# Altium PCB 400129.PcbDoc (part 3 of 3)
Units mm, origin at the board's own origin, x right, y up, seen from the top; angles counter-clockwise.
Board outline 295.85 x 54.86 mm, 2 copper layers (Top Layer, Bottom Layer), stack 1.671 mm thick; 222 components, 127 nets, 693 pads, 1827 vias.
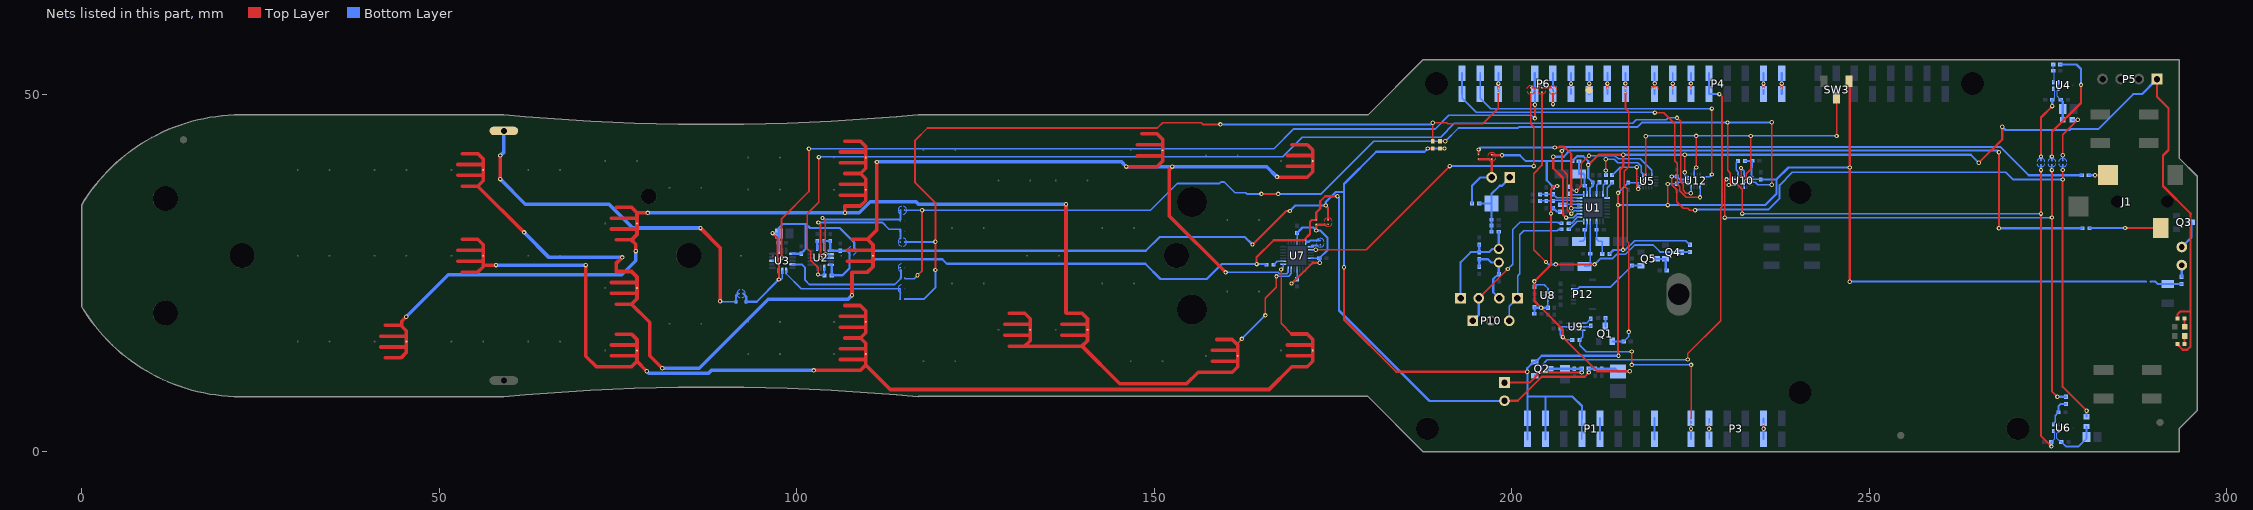
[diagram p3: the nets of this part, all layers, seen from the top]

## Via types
v1: diameter 0.61, hole 0.305, Top Layer to Bottom Layer, tented both sides, 1823 vias
v2: diameter 0.6, hole 0.3, Top Layer to Bottom Layer, tented both sides, 4 vias

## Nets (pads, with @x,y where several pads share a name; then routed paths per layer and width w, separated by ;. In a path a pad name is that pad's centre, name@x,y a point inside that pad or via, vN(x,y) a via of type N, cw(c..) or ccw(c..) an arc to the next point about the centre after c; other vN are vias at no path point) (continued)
KEYOUT_5: K6.2 K14.2 K19.2 K26.2 K31.2 K37.2 K45.2 U7.20 | length 159.3
  Top Layer w0.203: 161.659,14.956 161.659,15.218 v1(162.244,15.803) ; v1(165.538,19.089) 165.538,21.454 167.081,22.997 v1(167.081,24.547)
  Top Layer w0.508: 44.78,17.585 44.78,18.284 v1(45.385,18.89) ; 76.897,29.646 77.49,29.053 v1(77.49,28.079) ; 77.659,33.456 79.144,33.456 v1(79.173,33.428) ; 106.738,34.377 106.738,33.433 v1(106.74,33.431) ; 131.897,14.797 137.738,14.797 ; v1(137.659,34.625) 137.659,19.447 137.738,19.369 ; 139.897,14.797 145.168,9.526 154.511,9.526 156.131,11.146 158.738,11.146
  Bottom Layer w0.203: v1(162.244,15.803) 162.252,15.803 v1(165.538,19.089) ; v1(167.081,24.547) 167.124,24.59 168.77,24.59 168.838,24.658 168.847,24.648 169.157,24.959 U7.20@169.157,25.536
  Bottom Layer w0.508: v1(45.385,18.89) 51.267,24.772 75.548,24.772 77.49,26.714 v1(77.49,28.079) ; v1(79.173,33.428) v1@106.708,33.428 ; v1(106.74,33.431) 108.748,33.431 110.28,34.963 116.675,34.963 117.014,34.625 v1(137.659,34.625)
KEYOUT_6: K7.2 K15.2 K27.2 K38.2 K46.2 U7.21 | length 171.4
  Top Layer w0.508: 55.397,37.146 55.41,37.146 61.854,30.702 v1(61.88,30.702) ; 74.738,25.218 74.738,26.345 v1(75.593,27.199) ; 76.897,20.646 79.433,18.11 79.433,13.454 v1(81.189,11.698) ; v1(107.727,21.916) 107.727,25.127 107.742,25.142 107.738,25.146 ; 109.897,29.718 111.202,31.023 v1(111.202,40.53) ; v1(146.081,39.893) 146.084,39.896 148.238,39.896 ; v1(152.513,39.896) 152.117,39.5 152.117,32.968 v1(159.977,25.107) ; v1(167.173,38.455) 167.232,38.396 169.238,38.396
  Bottom Layer w0.203: v1(159.977,25.107) 167.336,25.107 167.5,24.943 168.504,24.943 168.757,25.197 U7.21@168.757,25.536
  Bottom Layer w0.508: v1(61.88,30.702) 61.88,30.676 65.356,27.199 v1(75.593,27.199) ; v1(81.189,11.698) 86.35,11.698 96.005,21.353 107.164,21.353 v1(107.727,21.916) ; v1(111.202,40.53) 111.269,40.597 145.377,40.597 v1(146.081,39.893) 165.735,39.893 v1(167.173,38.455)
KEYOUT_7: K8.2 K16.2 K20.2 K28.2 K47.2 U7.22 | length 136
  Top Layer w0.203: v1(167.731,25.5) 167.731,17.987 169.238,16.48
  Top Layer w0.508: 56.159,25.908 56.366,26.115 v1(57.943,26.115) ; v1(70.495,26.117) 70.509,26.103 70.509,13.392 72.006,11.896 74.738,11.896 ; 77.659,12.658 v1@79.032,11.285 ; v1(102.376,11.396) 106.738,11.396 ; 109.659,13.432 109.659,12.154 113.09,8.722 166.052,8.722 169.238,11.908
  Bottom Layer w0.203: v1(167.731,25.5) 168.032,25.801 U7.22@168.032,26.261
  Bottom Layer w0.508: v1(57.943,26.115) v1(57.943,26.115) v1(70.495,26.117) ; v1(79.037,11.289) 79.314,11.012 87.652,11.012 88.036,11.396 v1(102.376,11.396)
LIS3DH_INT1: P6.6 U3.11 | length 128.3
  Top Layer w0.254: v1(97.886,27.134) 97.886,32.602 101.702,36.418 v1(101.702,42.393) ; v1(203.225,46.634) v1(203.225,48.539)
  Bottom Layer w0.254: U3.11@96.599,26.721 97.279,26.721 97.692,27.134 v1(97.886,27.134) ; v1(101.702,42.393) 166.743,42.393 169.511,45.16 179.503,45.16 179.507,45.156 189.267,45.156 191.189,47.078 202.746,47.078 203.194,46.63 203.221,46.63 v1(203.225,46.634) ; P6.6@203.196,50.038 203.225,50.009 v1(203.225,48.539)
  Bottom Layer w0.305: P6.6@203.196,50.038 P6.6@203.196,52.968
MIC_CLK: R24.1 SB34.2 U10.7 | length 86.2
  Top Layer w0.203: v1(229.766,32.759) v1(229.766,32.759) 229.768,37.861 v1(230.019,38.112)
  Top Layer w0.254: v1(275.514,39.402) 275.514,8.478 v1(276.283,7.71)
  Bottom Layer w0.203: v1@229.766,32.769 v1(275.515,32.769) ; v1(230.019,38.112) 231.042,38.112 U10.7@231.049,38.105 ; v1(275.514,39.402) 275.514,39.963 SB34.2@275.514,40.137
  Bottom Layer w0.305: v1(276.283,7.71) R24.1@277.507,7.709
MIC_DOUT: C44.2 SB35.2 U6.4 U10.11 | length 92.2
  Top Layer w0.203: v1(232.048,39.698) 232.048,38.674 231.47,38.095 231.47,37.494 232.212,36.751 232.212,33.322 v1(232.213,33.32)
  Top Layer w0.254: v1(273.988,39.402) 273.988,2.236 v1(275.449,0.775)
  Bottom Layer w0.152: C44.2@275.449,1.388 275.892,1.832 275.892,2.758 U6.4@275.713,2.936
  Bottom Layer w0.203: v1(232.048,39.698) 232.474,39.272 U10.11@232.474,38.73 ; v1@232.213,33.325 v1(274,33.323) v1(274,33.323)
  Bottom Layer w0.254: v1(273.988,39.402) SB35.2@273.988,40.137 ; v1(275.449,0.775) C44.2@275.449,1.388
NetBat1_1: Bat1.1 D1.1 SB7.2 | length 52.8
  Top Layer w0.508: v1(58.547,38.151) 58.551,38.155 v1(58.551,41.444) ; v1(86.546,31.296) 89.281,28.561 v1(89.281,21.057)
  Bottom Layer w0.254: v1(89.281,21.057) 89.329,21.008 D1.1@91.528,21.008 91.528,21.927 91.735,22.134 SB7.2@91.903,22.134
  Bottom Layer w0.508: v1(58.547,38.151) 62.052,34.646 72.307,34.646 72.31,34.642 73.742,34.642 77.083,31.301 86.541,31.301 v1(86.546,31.296) ; v1(58.551,41.444) 59.05,41.943 Bat1.1@59.05,44.882
NetC2_2: C2.2 C3.2 P2.1 Q2.3 R3.1 | length 16.5
  Top Layer w0.305: P2.1@198.973,9.952 199.234,9.691 202.495,9.691 203.905,11.101 v1(209.773,11.101)
  Bottom Layer w0.305: Q2.3@205.294,11.624 207.425,11.624 C2.2@207.438,11.637 207.44,11.635 C3.2@208.743,11.635 208.746,11.633 R3.1@209.773,11.633 v1(209.773,11.101)
NetC6_2: C6.2 R4.2 U10.13 | length 3.2
  Bottom Layer w0.254: U10.13@233.499,38.505 233.499,39.678 233.598,39.778 C6.2@233.598,40.695
  Bottom Layer w0.305: R4.2@232.617,40.695 C6.2@233.598,40.695
NetC7_1: C7.1 C8.2 C9.2 P9.1 R5.1 R6.2 | length 10.8
  Bottom Layer w0.305: R5.1@195.439,34.74 197.151,34.74 C7.1@197.157,34.734 ; R6.2@197.161,30.789 197.161,31.654 C8.2@197.157,31.658 197.157,32.492 C7.1@197.157,34.734 ; P9.1@199.461,38.381 P9.1@199.722,38.381 199.722,38.335 198.614,37.227 198.307,37.227 197.166,36.086 C7.1@197.166,34.726 C7.1@197.157,34.734
NetC10_1: C10.1 J1.2 | length 2.7
  Top Layer w0.305: v1(281.543,38.699) 281.546,38.696 J1.2@283.355,38.696
  Bottom Layer w0.305: C10.1@280.693,38.689 280.703,38.699 v1(281.543,38.699)
NetC10_2: C10.2 U1.24 | length 85.2
  Top Layer w0.254: v1@207.012,42.085 207.012,39.508 207.741,38.78 207.741,33.853 208.27,33.323 v1(208.322,33.323)
  Bottom Layer w0.203: v1(208.322,33.323) 208.322,33.351 208.498,33.528 208.53,33.528 208.717,33.714 209.47,33.714 U1.24@209.475,33.709
  Bottom Layer w0.305: v1(207.001,42.085) 207.536,42.62 268.347,42.62 272.278,38.689 C10.2@279.693,38.689
NetC11_1: C11.1 J1.3 | length 10
  Top Layer w0.305: v1(285.76,31.303) 285.767,31.296 J1.3@290.755,31.296
  Bottom Layer w0.305: C11.1@280.786,31.281 280.808,31.303 v1(285.76,31.303)
NetC11_2: C11.2 U1.23 | length 96.5
  Top Layer w0.305: v1@205.797,41.367 205.797,39.662 207.159,38.3 207.159,33.191 v1(207.585,32.765) ; v1(268.111,31.281) v1(268.111,41.91)
  Bottom Layer w0.203: v1(207.585,32.765) 207.583,32.767 208.553,32.767 209.044,33.259 U1.23@209.475,33.259
  Bottom Layer w0.305: v1(205.797,41.267) 207.247,41.267 208.117,42.137 267.884,42.137 v1(268.111,41.91) ; v1(268.111,31.281) C11.2@279.786,31.281
NetC12_1: C12.1 JP1.2 P10.1 | length 22.4
  Top Layer w0.254: JP1.2@195.375,21.502 v1(199.446,25.573)
  Bottom Layer w0.254: v1(199.446,25.573) 200.13,26.257 200.13,31.104 201.144,32.118 206.421,32.118 206.543,31.996 C12.1@206.958,31.996
  Bottom Layer w0.305: P10.1@194.551,18.321 195.375,19.145 JP1.2@195.375,21.502
NetC12_2: C12.2 U1.22 | length 1.9
  Bottom Layer w0.203: C12.2@207.958,31.996 208.348,31.996 209.161,32.809 U1.22@209.475,32.809
NetC13_2: C13.2 R10.1 R11.2 U1.27 | length 5.5
  Bottom Layer w0.203: R11.2@203.925,35.242 204.078,35.089 C13.2@204.68,35.089 ; C13.2@204.832,35.089 R10.1@205.725,35.09 ; R10.1@205.776,35.168 208.468,35.168 208.578,35.059 U1.27@209.475,35.059
NetC14_2: C14.2 R9.1 R13.2 U1.28 | length 5.9
  Bottom Layer w0.203: R13.2@203.925,36.025 C14.2@204.832,36.025 R9.1@205.725,36.025 ; R9.1@205.725,36.177 205.668,36.12 206.266,35.522 209.462,35.522 U1.28@209.475,35.509
NetC15_2: C15.2 C16.2 JP1.1 P11.1 R6.1 | length 14.6
  Bottom Layer w0.305: JP1.1@192.835,21.502 192.835,26.528 194.241,27.934 C16.2@195.451,27.934 ; C15.2@195.452,28.986 C16.2@195.451,27.934 C16.2@195.451,27.934 ; R6.1@198.161,30.789 198.161,28.4 P11.1@198.179,28.382 197.262,28.382 196.815,27.934 C16.2@195.451,27.934
NetC16_1: C16.1 C18.2 JP2.2 P11.2 R17.2 | length 9.7
  Bottom Layer w0.305: C18.2@195.449,25.882 195.451,25.884 C16.1@195.451,26.934 196.66,26.934 197.113,26.482 P11.2@198.179,26.482 ; P11.2@198.178,26.481 R17.2@198.178,24.848 198.088,24.848 197.41,24.17 197.41,22.33 JP2.2@198.246,21.494
NetC17_1: C17.1 JP2.1 P10.3 | length 18.8
  Bottom Layer w0.254: P10.3@199.631,18.321 199.631,20.341 200.784,21.494 JP2.1@200.786,21.494 200.839,21.546 200.839,24.652 201.109,24.923 201.109,30.391 201.635,30.917 206.337,30.917 206.541,31.121 C17.1@206.958,31.121
NetC17_2: C17.2 U1.21 | length 2.6
  Bottom Layer w0.203: C17.2@207.958,31.121 208.008,31.121 209.121,32.234 U1.21@210.05,32.234
NetC19_1: C19.1 C23.2 FB1.1 U1.2 | length 5.4
  Bottom Layer w0.203: C23.2@210.187,37.234 210.5,36.921 U1.2@210.5,36.084
  Bottom Layer w0.305: FB1.1@209.396,40.658 209.396,38.897 C19.1@209.391,38.891 209.978,38.891 210.161,38.708 210.161,37.234 C23.2@210.187,37.234
NetC20_1: C20.1 C25.2 R12.1 U1.17 | length 5.2
  Bottom Layer w0.203: U1.17@211.85,32.234 211.85,31.086 C25.2@211.853,31.083 211.853,29.727 212.146,29.433 C20.1@212.664,29.433 212.659,29.428 R12.1@212.659,27.691
NetC21_1: C21.1 C26.2 U1.19 | length 7
  Bottom Layer w0.203: C21.1@210.145,25.957 210.739,25.957 210.947,26.164 C26.2@210.947,27.734 210.95,27.738 U1.19@210.95,32.234
NetC22_1: C22.1 C27.2 U1.20 | length 3.5
  Bottom Layer w0.203: C22.1@209.41,29.433 209.902,29.433 210.212,29.744 C27.2@210.212,31.083 210.5,31.371 U1.20@210.5,32.234
NetC34_2: C34.2 U2.14 | length 1.1
  Bottom Layer w0.305: U2.14@102.856,28.366 C34.2@102.856,29.485
NetC35_2: C35.2 C36.2 FB2.1 U4.2 U4.3 | length 5.7
  Bottom Layer w0.152: U4.2@276.41,51.703 U4.3@276.41,50.803 276.41,50.692 276.24,50.522 276.24,49.762 276.738,49.264 C35.2@276.778,49.264
  Bottom Layer w0.305: C35.2@276.778,49.264 277.035,49.006 C36.2@277.035,47.969 277.035,46.434 FB2.1@277.041,46.428
NetC37_2: C37.2 R23.2 SB28.2 | length 4.5
  Bottom Layer w0.305: SB28.2@289.345,23.819 289.981,23.819 290.316,23.484 C37.2@291.719,23.484 291.728,23.492 R23.2@293.674,23.492
NetC39_2: C39.2 SB35.1 U4.4 | length 10.9
  Top Layer w0.305: v1(273.99,41.302) 273.99,46.76 v1(275.581,48.351)
  Bottom Layer w0.152: C39.2@275.59,49.268 275.944,49.622 275.944,50.453 275.71,50.687 U4.4@275.71,50.803
  Bottom Layer w0.305: SB35.1@273.988,40.762 273.988,40.937 273.988,41.3 v1(273.99,41.302) ; v1(275.581,48.351) 275.581,49.259 C39.2@275.59,49.268
NetC40_2: C40.2 R22.2 U4.1 | length 2.6
  Bottom Layer w0.152: R22.2@275.701,54.174 C40.2@275.701,53.285 275.88,53.107 275.88,52.024 275.71,51.854 U4.1@275.71,51.703
NetC42_2: C42.2 C43.2 FB3.1 U6.3 | length 7.9
  Bottom Layer w0.152: U6.3@276.413,2.936 276.413,2.84 276.183,2.609 276.183,1.925 276.72,1.388 C42.2@276.838,1.388
  Bottom Layer w0.254: C42.2@276.838,1.388 277.453,0.772 279.273,0.772 279.636,1.135 280.373,1.873 C43.2@280.373,2.08 FB3.1@280.373,3.56
NetC45_2: C45.2 R24.2 U6.1 | length 4.1
  Bottom Layer w0.203: U6.1@275.713,3.836 275.713,3.962 275.987,4.235 275.987,5.082 C45.2@276.438,5.533
  Bottom Layer w0.305: C45.2@276.438,5.533 276.429,5.542 276.429,6.38 276.759,6.709 R24.2@277.507,6.709
NetC46_2: C46.2 C47.2 C48.2 SB29.2 SB30.2 U7.4 U7.12 U7.18 | length 21.1
  Top Layer w0.305: v1(169.185,23.55) 169.242,23.55 172.143,26.452 v1(173.126,26.452) ; v1(172.652,30.961) 172.655,30.964 172.655,31.756 173.912,31.756 173.963,31.807
  Bottom Layer w0.203: U7.18@169.957,25.536 169.957,24.132 C47.2@169.96,24.129 ; U7.4@169.957,29.386 C46.2@169.957,30.442 ; U7.12@171.882,27.061 171.885,27.064 C48.2@173.083,27.064
  Bottom Layer w0.305: v1(169.185,23.55) 169.237,23.55 169.816,24.129 C47.2@169.96,24.129 ; C46.2@169.953,30.612 170.725,31.384 172.229,31.384 v1(172.652,30.961) 172.672,30.941 173.233,30.941 174.225,29.949 174.225,28.205 C48.2@173.083,27.064 173.126,27.021 v1(173.126,26.452)
NetC49_1: C49.1 U9.4 | length 1.4
  Bottom Layer w0.254: U9.4@209.907,18.003 210.438,18.003 C49.1@211.057,18.622
NetC49_2: C49.2 U9.5 | length 1.2
  Bottom Layer w0.254: U9.5@209.907,17.503 210.938,17.503 C49.2@211.057,17.622
NetFB2_2: FB2.2 SB27.2 | length 7.3
  Top Layer w0.254: v1(277.038,41.478) 277.038,44.331 v1(279.144,46.437)
  Bottom Layer w0.254: v1(277.038,41.478) 277.041,41.475 SB27.2@277.041,40.767
  Bottom Layer w0.305: FB2.2@278.391,46.428 278.397,46.435 v1(279.144,46.437)
NetLD1_1: LD1.1 Q3.3 | length 4
  Bottom Layer w0.305: LD1.1@293.691,28.661 295.049,30.018 Q3.3@295.049,32.098
NetLD1_2: LD1.2 R23.1 | length 1.6
  Bottom Layer w0.305: R23.1@293.674,24.492 293.674,26.104 LD1.2@293.691,26.121
NetLD3_2: LD3.2 R36.1 | length 1.1
  Top Layer w0.305: LD3.2@294.068,16.219 294.073,16.215 R36.1@294.073,15.088
NetLD4_2: LD4.2 R37.1 | length 1.2
  Top Layer w0.305: LD4.2@294.068,17.503 294.068,18.664 R37.1@294.073,18.669
NetP3_1: P3.1 SB14.2 | length 3.5
  Top Layer w0.203: v1(225.044,3.243) 225.081,3.28 225.081,3.627 SB14.2@225.081,3.802
  Bottom Layer w0.254: P3.1@225.04,1.778 P3.1@225.04,4.708
NetP3_2: P3.2 SB1.2 | length 3.5
  Top Layer w0.203: v1(227.593,3.243) 227.622,3.272 SB1.2@227.622,3.802
  Bottom Layer w0.203: P3.2@227.58,1.778 P3.2@227.58,4.708
NetP3_5: P3.5 SB2.2 | length 3.5
  Top Layer w0.254: v1(235.204,3.243) 235.211,3.25 SB2.2@235.211,3.802
  Bottom Layer w0.254: P3.5@235.2,1.778 P3.5@235.2,4.708
NetP4_1: P4.1 SB33.2 | length 3.5
  Top Layer w0.305: SB33.2@237.739,50.927 v1(237.739,51.502)
  Bottom Layer w0.305: P4.1@237.74,50.038 P4.1@237.74,52.968
NetP4_2: P4.2 SB3.2 | length 3.5
  Top Layer w0.305: SB3.2@235.196,50.932 v1(235.196,51.498)
  Bottom Layer w0.305: P4.2@235.2,50.038 P4.2@235.2,52.968
NetP4_6: P4.6 SB4.2 | length 3.5
  Top Layer w0.254: v1(225.04,51.511) 225.044,51.507 225.044,51.102 SB4.2@225.044,50.927
  Bottom Layer w0.305: P4.6@225.04,50.038 v1(225.04,51.511) P4.6@225.04,52.968
NetP4_7: P4.7 SB5.2 | length 3.5
  Top Layer w0.254: SB5.2@222.5,50.935 222.5,51.11 v1(222.5,51.503)
  Bottom Layer w0.254: P4.7@222.5,50.038 v1(222.5,51.503) P4.7@222.5,52.968
NetP4_8: P4.8 SB6.2 | length 3.6
  Top Layer w0.305: SB6.2@219.96,50.876 219.96,51.051 219.96,51.524 v1(219.975,51.539)
  Bottom Layer w0.305: P4.8@219.96,50.038 P4.8@219.96,52.968
NetP6_1: P6.1 SB10.2 | length 3.6
  Top Layer w0.305: v1(215.88,51.521) 215.885,51.516 SB10.2@215.885,50.877
  Bottom Layer w0.305: P6.1@215.896,50.038 P6.1@215.896,52.968
NetP6_2: P6.2 SB9.2 | length 3.5
  Top Layer w0.305: SB9.2@213.346,50.928 213.346,51.493 v1(213.356,51.503)
  Bottom Layer w0.305: P6.2@213.356,50.038 v1(213.356,51.503) P6.2@213.356,52.968
NetP6_3: P6.3 TP2.1 | length 3.9
  Top Layer w0.305: TP2.1@210.816,50.579 v1(210.816,51.503)
  Bottom Layer w0.305: P6.3@210.816,50.038 v1(210.816,51.503) P6.3@210.816,52.968
NetP6_4: P6.4 SB32.2 | length 3.5
  Top Layer w0.203: v1(208.276,51.503) 208.28,51.499 208.28,51.158 SB32.2@208.28,50.983
  Bottom Layer w0.254: P6.4@208.276,50.038 v1(208.276,51.503) P6.4@208.276,52.968
NetP6_5: P6.5 SB11.2 | length 6
  Top Layer w0.305: SB11.2@205.741,50.305 205.741,50.13 205.741,48.64 v1(205.753,48.629)
  Bottom Layer w0.305: P6.5@205.736,52.968 P6.5@205.736,50.038 205.753,50.021 v1(205.753,48.629)
NetP6_8: P6.8 SB12.2 | length 3.6
  Top Layer w0.305: SB12.2@198.102,50.879 198.102,51.489 v1@198.115,51.502
  Bottom Layer w0.305: P6.8@198.116,50.038 v1(198.116,51.503) P6.8@198.116,52.968
NetP9_2: P9.2 R5.2 SB15.2 SB16.2 | length 9.8
  Top Layer w0.305: SB16.2@195.34,40.912 196.876,40.912 ; P9.2@197.182,38.381 197.195,38.394 197.195,40.778 SB15.2@197.195,40.952
  Bottom Layer w0.305: R5.2@194.439,34.74 194.439,37.231 195.589,38.381 P9.2@197.182,38.381
NetQ1_1: Q1.1 R31.2 SB10.1 | length 37.4
  Top Layer w0.254: SB10.1@215.885,50.252 215.885,48.046 216.338,47.592 216.338,39.836 215.727,39.225 215.727,37.225 216.129,36.823 216.129,29.44 216.358,29.211 216.358,16.796 v1(216.35,16.789)
  Bottom Layer w0.254: Q1.1@214.034,15.457 215.255,15.457 215.273,15.439 215.65,15.439 216.35,16.14 v1(216.35,16.789)
NetQ1_3: Q1.3 R2.1 | length 1.2
  Bottom Layer w0.254: Q1.3@213.084,17.557 213.1,17.573 R2.1@213.1,18.707
NetQ4_1: Q4.1 Q5.3 R34.2 | length 3.3
  Bottom Layer w0.305: Q5.3@220.176,26.996 Q4.1@221.492,26.995 221.221,26.995 221.516,26.7 R34.2@221.516,25.36
NetQ4_3: Q4.3 R33.2 SB38.1 | length 46.7
  Top Layer w0.254: SB38.1@204.203,50.31 204.203,50.135 204.203,40.067 203.06,38.925 203.06,28.272 v1(204.778,26.554) ; v1(206.145,26.221) v1(211.571,26.221)
  Bottom Layer w0.254: v1(204.778,26.554) 205.111,26.221 v1(206.145,26.221) ; v1(211.571,26.221) 212.384,27.034 214.046,27.034 214.656,27.643 215.895,27.643 217.185,28.933 219.757,28.933 220.74,27.951 223.583,27.951 223.585,27.953 Q4.3@223.592,27.945 ; Q4.3@223.6,27.953 R33.2@224.888,27.953
  Bottom Layer w0.305: Q4.3@223.592,27.945 Q4.3@223.6,27.953
NetR4_1: R4.1 U10.9 | length 2.2
  Bottom Layer w0.203: R4.1@231.617,40.695 231.385,40.463 231.385,39.424 231.674,39.135 U10.9@231.674,38.73
NetR7_1: R7.1 R8.2 U1.26 | length 2.8
  Bottom Layer w0.203: R7.1@206.705,34.628 207.573,34.628 207.592,34.609 208.029,34.609 208.061,34.64 209.444,34.64 U1.26@209.475,34.609
NetR14_1: R14.1 U5.4 | length 17.2
  Top Layer w0.203: v1(209.044,36.521) 209.719,37.196 209.719,40.359 v1(210.782,41.422)
  Bottom Layer w0.203: R14.1@208.066,37.091 208.636,36.521 v1(209.044,36.521) ; v1(210.782,41.422) 210.805,41.446 214.398,41.446 214.853,40.99 217.922,40.99 219.536,39.377 U5.4@219.536,38.68
NetR14_2: R14.2 U1.1 | length 2.1
  Bottom Layer w0.203: R14.2@208.066,36.091 208.169,35.988 210.039,35.988 210.05,35.999 U1.1@210.05,36.084
NetR15_1: R15.1 U1.5 | length 1.8
  Bottom Layer w0.203: U1.5@211.85,36.084 211.85,37.301 R15.1@212.241,37.691
NetR16_1: R16.1 U5.1 | length 8.9
  Top Layer w0.203: v1(213.138,40.912) 213.138,39.36 v1(213.144,39.355)
  Bottom Layer w0.203: R16.1@213.138,38.708 213.144,38.713 v1(213.144,39.355) ; v1(213.138,40.912) 214.323,40.912 214.805,40.431 217.615,40.431 218.086,39.96 218.086,39.135 218.336,38.885 U5.1@218.336,38.68
NetR16_2: R16.2 U1.7 | length 1.8
  Bottom Layer w0.203: U1.7@212.75,36.084 212.75,37.32 R16.2@213.138,37.708
NetR18_1: R18.1 U5.13 | length 7.2
  Top Layer w0.203: 217.465,37.028 v1(217.465,39.825)
  Bottom Layer w0.203: R18.1@214.023,38.714 215.133,39.825 v1(217.465,39.825) ; v1(217.679,36.782) 217.711,36.814 U5.13@217.711,37.255
NetR18_2: R18.2 U1.8 | length 2.5
  Bottom Layer w0.203: U1.8@213.325,35.509 213.325,36.925 214.023,37.622 R18.2@214.023,37.714
NetR19_1: R19.1 U2.6 U12.12 | length 154.7
  Top Layer w0.203: v1(102.978,24.811) 102.978,25.775 101.956,26.797 101.956,27.976 101.488,28.443 101.488,33.285 103.099,34.896 v1(103.099,41.224) ; v1(223.092,46.708) 223.585,46.215 223.585,37.796 223.947,37.433 223.947,36.573 224.351,36.17 v1(225.019,36.17) ; v1(103.099,41.224) 103.038,41.224 103.099,41.284 v1(103.099,41.224)
  Bottom Layer w0.203: v1(102.978,24.811) 103.096,24.693 103.712,24.693 103.856,24.837 U2.6@103.856,25.741 ; v1(103.099,41.224) 103.153,41.279 167.942,41.279 170.698,44.035 190.04,44.035 191.936,45.931 216.876,45.931 217.406,46.461 221.591,46.461 221.838,46.708 v1(223.092,46.708) ; v1(225.019,36.17) 225.116,36.267 U12.12@225.116,37.08
NetR20_1: R20.1 SB22.1 SB25.2 U10.5 U10.15 | length 161.4
  Top Layer w0.203: v1(230.166,46.072) 230.166,39.355 230.553,38.968 230.553,37.545 v1(230.323,37.315) ; v1(236.347,37.368) v1@236.395,37.415
  Top Layer w0.254: v1(116.886,24.7) 117.534,25.347 v1(117.534,33.781) ; v1(164.977,36.083) 167.335,36.083 v1(167.336,36.082) ; R20.1@189.949,43.435 v1(190.676,43.435) ; v1(236.347,37.368) v1(236.347,46.086)
  Bottom Layer w0.203: v1(230.323,37.315) 230.333,37.305 U10.5@231.049,37.305 ; U10.15@233.499,37.705 234.056,37.705 234.393,37.368 v1(236.347,37.368)
  Bottom Layer w0.254: SB22.1@115.138,33.781 115.046,33.782 v1(117.534,33.781) ; 115.143,24.217 116.404,24.217 v1(116.886,24.7) ; v1(117.534,33.781) 149.473,33.781 153.244,37.552 159.114,37.552 159.306,37.744 159.769,37.744 161.282,36.231 162.805,36.231 162.954,36.082 v1(164.977,36.083) v1(164.977,36.083) ; v1(167.336,36.082) 173.357,36.082 180.711,43.435 v1(190.676,43.435) 192.536,45.296 200.864,45.296 200.987,45.418 217.556,45.418 218.209,46.072 v1(230.166,46.072) 230.175,46.062 236.323,46.062 v1(236.347,46.086)
NetR21_1: R21.1 SB12.1 SB23.1 SB26.2 | length 119.5
  Top Layer w0.254: v1(119.383,25.444) v1(119.383,29.386) 119.383,34.83 116.547,37.665 116.547,43.557 118.288,45.297 150.421,45.297 151.154,46.03 151.159,46.026 156.539,46.026 156.771,45.794 v1(159.241,45.794) ; R21.1@188.943,43.435 v1(188.943,46.027) 190.896,46.027 191.041,45.882 195.929,45.882 198.102,48.055 SB12.1@198.102,50.254
  Bottom Layer w0.254: SB26.2@115.095,21.366 117.784,21.366 119.383,22.965 v1(119.383,25.444) ; SB23.1@115.11,29.347 119.344,29.347 v1(119.383,29.386) ; v1(159.241,45.794) 188.71,45.794 v1(188.943,46.027)
NetR22_1: R22.1 SB34.1 | length 17.6
  Top Layer w0.305: v1(275.515,41.302) 275.515,44.726 279.591,48.801 v1(279.591,51.329)
  Bottom Layer w0.305: SB34.1@275.514,40.762 275.514,40.937 275.514,41.301 v1(275.515,41.302) ; R22.1@276.701,54.174 278.974,54.174 279.6,53.549 279.591,53.54 v1(279.591,51.329)
NetR25_1: R25.1 SB14.1 U9.6 | length 27.9
  Top Layer w0.203: v1(216.758,12.166) 216.764,12.172 v1(216.764,14.046) ; v1(225.069,12.167) 225.081,12.155 SB14.1@225.081,4.477
  Bottom Layer w0.203: U9.6@209.907,17.003 209.907,16.104 R25.1@209.467,15.664 209.467,14.888 210.375,13.98 216.765,13.98 216.765,14.044 v1(216.764,14.046) ; v1(216.758,12.166) v1(225.069,12.167)
NetR26_1: R26.1 U7.23 | length 1.6
  Bottom Layer w0.203: R26.1@166.681,26.169 167.173,26.661 U7.23@168.032,26.661
NetSB19_1: SB19.1 SB25.1 U3.4 | length 18.7
  Bottom Layer w0.254: U3.4@99.399,26.221 100.686,26.221 101.16,25.747 101.16,24.008 101.759,23.409 113.71,23.409 114.37,24.068 ; 114.518,24.217 114.574,24.273 114.574,24.607 114.574,25.085 114.574,25.438
NetSB20_1: SB20.1 SB22.2 U2.2 | length 18.1
  Top Layer w0.254: v1(103.599,32.705) 103.994,32.31 v1(103.994,27.641)
  Bottom Layer w0.254: v1(103.599,32.705) 103.811,32.493 114.518,32.493 114.518,33.424 114.518,33.776 SB22.2@114.513,33.781 ; v1(103.994,27.641) U2.2@104.581,27.641
NetSB21_1: SB21.1 SB23.2 U2.3 | length 19.6
  Top Layer w0.254: v1(103.022,32.08) 103.342,31.761 v1(103.342,27.143)
  Bottom Layer w0.254: v1(103.022,32.08) 103.003,32.1 111.946,32.1 112.904,31.142 114.518,31.142 114.513,31.137 114.513,30.161 114.513,29.808 ; v1(103.342,27.143) 103.402,27.082 104.225,27.082 104.285,27.142 104.286,27.141 U2.3@104.581,27.141
NetSB24_1: SB24.1 SB26.1 U3.6 | length 18.7
  Bottom Layer w0.254: U3.6@98.499,25.321 98.499,24.943 100.619,22.823 114.17,22.823 SB24.1@114.463,22.823 114.47,22.815 114.47,22.32 SB26.1@114.47,21.366
NetSB31_1: SB31.1 U7.8 | length 0.9
  Bottom Layer w0.3: U7.8@171.942,28.721 172.102,28.881 172.796,28.881
NetSB31_2: SB31.2 U7.7 | length 2
  Bottom Layer w0.305: U7.7@171.224,29.386 171.633,29.386 171.81,29.564 172.692,29.564 SB31.2@173.187,29.564
NetSB36_2: SB36.2 U7.9 | length 46.6
  Top Layer w0.203: v1(172.569,28.265) 179.623,28.265 191.311,39.953 v1(191.311,39.962) ; SB36.2@202.648,50.305 SB36.2@202.648,50.319
  Top Layer w0.254: SB36.2@202.648,50.305 202.648,50.13 202.648,45.865 203.06,45.454 v1(203.06,39.96)
  Bottom Layer w0.152: U7.9@171.882,28.261 172.566,28.261 v1(172.569,28.265)
  Bottom Layer w0.254: v1(191.311,39.962) 191.302,39.962 191.3,39.96 v1(203.06,39.96)
NetSW3_2: SW3.2 U5.2 U10.2 U12.2 | length 52
  Top Layer w0.203: v1@218.539,37.919 v1(218.542,37.922) 218.542,38.805 218.736,38.999 v1(218.736,44.146) ; v1(225.787,39.78) v1@225.787,44.188 ; v1(232.774,37.905) 232.774,38.905 233.407,39.538 v1@233.407,44.173 ; v1(233.408,44.17) v1@233.408,44.172 ; v1(245.415,44.17) SW3.2@245.415,49.523
  Bottom Layer w0.203: v1@218.736,38.121 U5.2@218.736,38.68 ; v1(218.736,44.146) 218.777,44.188 v1(225.778,44.188) 245.397,44.188 v1(245.415,44.17) ; U12.2@225.516,38.73 225.516,39.508 v1(225.787,39.78) ; U10.2@232.474,37.08 232.474,37.591 232.774,37.891 v1(232.774,37.905)
"POWER ON/OFF": P4.5 Q2.1 | length 66.3
  Top Layer w0.254: v1(224.595,12.914) 224.595,13.757 229.208,18.37 229.208,34.115 229.403,34.311 229.403,49.648 v1(229.022,50.029)
  Bottom Layer w0.254: Q2.1@203.194,10.674 203.354,10.674 204.149,11.469 204.149,12.082 204.955,12.888 224.569,12.888 v1(224.595,12.914) ; P4.5@227.58,52.968 P4.5@227.58,50.038 229.013,50.038 v1(229.022,50.029)
SCL: P6.10 U12.9 | length 49.1
  Top Layer w0.203: v1(220.004,47.444) 221.245,47.444 222.793,45.897 222.793,40.709 223.118,40.384 223.118,37.437 223.47,37.085 223.47,36.522 224.395,35.597 v1(226.31,35.597)
  Bottom Layer w0.203: P6.10@193.036,50.038 193.036,49.445 195.006,47.474 219.974,47.474 v1(220.004,47.444) ; v1(226.31,35.597) 226.316,35.603 U12.9@226.316,37.097
  Bottom Layer w0.254: P6.10@193.036,50.038 P6.10@193.036,52.968
SDA: P6.9 U12.5 | length 46.9
  Top Layer w0.203: v1(227.977,38.795) v1(227.977,48.003)
  Bottom Layer w0.203: P6.9@195.576,49.469 197.042,48.003 220.943,48.003 v1(227.977,48.003) ; U12.5@226.941,38.505 227.687,38.505 v1(227.977,38.795)
  Bottom Layer w0.254: P6.9@195.576,49.469 P6.9@195.576,50.038 P6.9@195.576,52.968
V5V: P1.5 | length 2.9
  Bottom Layer w0.305: P1.5@212.34,1.778 P1.5@212.34,4.708
VCC: C1.1 C4.2 C5.2 C24.2 C50.2 C53.2 FB1.2 P2.2 P5.1 R3.2 R7.2 R9.2 R10.2 R12.2 R25.2 R26.2 R27.1 R28.1 R32.1 R33.1 R36.2 R37.2 SB15.1 SB17.1 SB29.1 U1.3 U8.1 U8.5 U9.2 U12.16 | length 377.1
  Top Layer w0.254: v1(224.178,39.084) 224.182,39.087 v1(224.182,41.55)
  Top Layer w0.305: v1(164.303,26.266) 164.303,27.204 166.701,29.601 170.915,29.601 171.776,30.463 171.776,32.173 172.035,32.432 SB29.1@172.655,32.432 172.655,33.479 173.207,34.031 173.207,35.051 173.91,35.753 v1(175.599,35.753) ; SB15.1@197.195,41.577 197.305,41.468 197.305,41.474 198.606,41.474 v1(198.615,41.484) ; P2.2@198.972,7.151 200.825,7.151 204.191,10.516 210.183,10.516 v1(210.767,11.101) ; v1(206.33,37.177) 205.928,37.177 205.481,36.73 205.481,33.341 v1(205.468,33.341) 205.468,26.16 v1(203.156,23.848) 203.156,21.103 v1(204.099,20.16) 207.14,17.119 v1(207.14,16.051) 211.922,11.269 v1(216.488,11.269) ; v1(210.688,40.13) 212.11,41.552 v1(215.583,41.552) 215.583,39.888 215.102,39.408 215.102,36.988 215.539,36.552 v1(215.539,28.245) ; v1(265.304,40.424) 268.573,43.694 v1(268.573,45.467) ; P5.1@290.223,52.14 290.223,49.66 291.84,48.043 291.84,42.223 291.056,41.439 291.056,37.193 294.937,33.312 294.898,33.273 294.912,33.259 294.912,19.634 ; R36.2@293.073,15.088 293.073,15.014 293.808,14.279 294.465,14.279 294.912,14.726 294.912,19.634 ; R37.2@293.073,18.669 293.073,19.236 293.472,19.634 294.912,19.634
  Bottom Layer w0.203: C50.2@205.052,20.163 U8.1@205.052,21.366 ; C53.2@206.812,17.253 207.062,17.503 U9.2@208.027,17.503 ; v1@207.14,16.059 207.535,15.664 R25.2@208.467,15.664
  Bottom Layer w0.254: R28.1@203.156,23.11 203.428,23.381 204.525,23.381 205.052,22.854 U8.5@205.052,22.466 ; v1(215.539,28.245) 215.885,28.245 217.171,29.53 224.307,29.53 R33.1@224.886,28.951 ; v1(224.178,39.084) 224.178,38.662 224.336,38.505 U12.16@224.491,38.505
  Bottom Layer w0.305: SB17.1@108.052,26.641 110.731,26.641 111.041,26.95 120.343,26.95 120.993,26.299 148.731,26.299 150.863,24.168 157.349,24.168 159.447,26.266 v1(164.303,26.266) 165.525,26.266 R26.2@165.656,26.134 ; v1(175.599,35.753) 175.819,35.533 175.819,19.786 188.493,7.112 198.972,7.112 P2.2@198.972,7.151 ; v1@198.72,41.589 v1(198.615,41.484) 201.125,41.484 201.951,40.658 FB1.2@208.446,40.658 208.446,40.678 209.11,41.342 209.985,41.342 210.688,40.639 v1(210.688,40.13) 210.688,38.34 C24.2@211.343,37.685 211.343,37.251 210.95,36.859 U1.3@210.95,36.084 ; R32.1@203.149,19.316 203.156,19.323 R27.1@203.156,20.241 203.234,20.163 C50.2@205.052,20.163 ; R28.1@203.156,23.11 v1(203.156,23.848) ; 204.871,40.658 204.871,37.968 205.662,37.177 v1(206.33,37.177) ; v1(205.468,33.341) 205.468,33.985 205.725,34.243 R10.2@205.725,34.188 ; R10.2@205.725,34.019 R10.2@205.725,34.188 ; R7.2@206.705,33.628 206.286,33.628 R10.2@205.725,34.188 ; C53.2@206.812,17.253 206.812,16.387 v1@207.14,16.059 ; v1(210.767,11.101) 210.773,11.106 R3.2@210.773,11.633 211.691,11.633 C4.2@211.693,11.631 C5.2@212.579,11.631 214.473,11.631 C1.1@214.838,11.266 216.486,11.266 v1(216.488,11.269) ; R12.2@213.659,27.691 214.213,28.245 v1(215.539,28.245) ; v1(265.304,40.424) 264.176,41.552 v1(215.583,41.552) ; v1(268.573,45.467) 269.035,45.005 278.031,45.005 278.166,45.14 281.988,45.14 286.879,50.031 288.114,50.031 P5.1@290.223,52.14 ; v1(215.583,41.552) 215.583,41.601 215.534,41.552 v1(215.583,41.552)
VCC_PDM: C52.2 FB3.2 SB27.1 U12.15 | length 100.9
  Top Layer w0.254: v1(222.354,38.505) 222.354,37.381 223.07,36.664 223.07,34.961 223.948,34.083 224.597,34.083 224.876,33.804 v1(225.629,33.804) ; v1(277.038,39.421) 277.038,38.112 277.026,38.1 277.026,9.097 v1(280.376,5.747)
  Bottom Layer w0.254: v1@222.354,38.505 C52.2@223.065,38.505 223.466,38.105 U12.15@224.491,38.105 ; v1(225.629,33.804) 225.704,33.879 235.873,33.879 237.438,35.444 237.438,37.316 239.228,39.106 269.048,39.106 270.053,38.1 v1(277.038,38.1) ; v1(277.038,39.421) 277.041,39.424 SB27.1@277.041,40.142 ; FB3.2@280.373,4.91 v1@280.373,5.718
VIN: P1.8 | length 2.9
  Bottom Layer w0.305: P1.8@219.96,1.778 P1.8@219.96,4.708
VIO: C28.2 C29.2 C33.2 C41.2 C55.2 C56.2 D1.3 P1.1 P1.2 P1.4 Q2.2 R20.2 R21.2 SB7.1 SB18.1 SB28.1 SB30.1 SW3.3 U3.1 U3.7 U3.8 U3.14 U5.14 U10.14 U12.14 | length 363.1
  Top Layer w0.203: v1(221.793,34.515) v1(221.793,37.465)
  Top Layer w0.305: v1(96.623,30.589) 97.301,29.911 97.301,26.747 97.499,26.55 v1(97.499,24.103) ; v1(163.73,28.996) 163.73,28.958 168.467,33.695 v1(168.958,33.695) ; v1(173.975,34.457) 173.963,34.446 174.297,34.112 174.297,32.728 SB30.1@174.297,32.435 ; v1(176.533,25.823) 176.533,18.511 183.836,11.209 202.151,11.209 v1(202.159,11.201) ; v1(188.25,42.43) 188.256,42.435 R21.2@188.943,42.435 ; R20.2@189.949,42.435 v1(190.581,42.435) ; v1(214.859,34.519) 214.859,34.528 v1@214.864,34.533 ; v1(214.864,36.215) v1@214.864,34.533 ; v1@214.88,34.549 v1@214.864,34.533 ; v1(214.919,13.447) 214.864,13.502 v1@214.864,34.533 ; SW3.3@247.165,51.823 246.942,51.6 247.244,51.299 v1(247.244,39.776) v1(247.244,23.8)
  Bottom Layer w0.203: v1(214.864,36.215) 214.864,36.249 C41.2@216.286,37.671 ; C41.2@216.3,37.638 216.301,37.655 U5.14@217.711,37.655 ; v1(221.793,37.465) 221.809,37.481 C56.2@223.065,37.481 223.289,37.705 U12.14@224.491,37.705 ; U10.14@233.499,38.105 C55.2@234.789,38.106
  Bottom Layer w0.229: v1(97.499,24.103) 97.849,24.103 97.999,24.253 U3.7@97.999,25.321 ; P1.4@209.8,1.778 P1.4@209.8,4.708
  Bottom Layer w0.305: SB7.1@92.528,22.134 92.928,21.734 D1.3@92.928,21.008 94.404,21.008 v1(97.499,24.103) U3.8@97.499,25.321 ; v1(96.623,30.589) 96.684,30.529 C29.2@97.496,30.529 97.496,31.305 98.079,31.888 101.272,31.888 ; C29.2@97.496,30.432 97.496,29.242 C28.2@97.499,29.239 U3.14@97.499,28.121 ; U3.1@99.399,27.721 100.455,27.721 100.462,27.728 100.663,27.728 100.762,27.827 100.762,27.915 100.987,28.14 100.989,28.14 101.272,28.423 101.272,31.888 ; v1(163.73,28.996) 162.666,30.06 150.754,30.06 148.825,28.131 SB18.1@108.042,28.131 108.042,29.281 106.008,31.315 101.845,31.315 101.272,31.888 ; v1(168.958,33.695) 169.72,34.457 v1(173.975,34.457) 173.975,34.955 175.357,36.337 176.533,36.337 ; v1(176.533,25.823) 176.533,37.469 181.05,41.986 187.806,41.986 v1(188.25,42.43) v1@190.581,42.43 ; P1.1@202.18,1.778 P1.1@202.18,4.708 202.18,7.732 ; P1.2@204.72,1.778 P1.2@204.72,4.708 204.72,7.685 204.673,7.732 ; P1.4@209.8,4.708 209.8,6.425 208.493,7.732 204.673,7.732 ; v1(214.859,34.519) 235.456,34.519 237.02,36.082 237.02,38.106 ; v1(214.919,13.447) 204.171,13.447 203.298,12.574 Q2.2@203.194,12.574 203.022,12.574 202.159,11.711 v1(202.159,11.201) 202.18,11.201 202.18,7.732 ; C55.2@234.789,38.106 237.02,38.106 ; v1(247.244,23.8) 247.263,23.819 SB28.1@288.681,23.819 ; v1(247.244,39.776) 238.691,39.776 237.02,38.106 ; 202.18,7.732 204.673,7.732
VMIC: SB16.1 U1.25 | length 23.1
  Top Layer w0.305: SB16.1@195.34,41.588 195.34,42.28 v1(195.351,42.291) ; v1(205.991,42.568) 206.542,42.568 206.644,42.669 207.304,42.669 208.3,41.674 v1(208.3,34.084) v1@208.42,34.084
  Bottom Layer w0.203: v1(208.3,34.084) 208.3,34.089 208.298,34.091 208.366,34.159 U1.25@209.475,34.159
  Bottom Layer w0.305: v1(195.351,42.291) 195.628,42.568 v1(205.991,42.568)
VU2: C30.2 C31.2 C32.2 R19.2 SB17.2 SB18.2 U2.1 U2.5 U2.16 | length 13.3
  Bottom Layer w0.305: U2.16@103.856,28.366 103.856,29.48 C30.2@103.851,29.485 104.694,29.485 C31.2@104.697,29.483 104.697,28.2 U2.1@104.756,28.141 ; U2.5@104.581,26.141 104.89,26.141 R19.2@104.89,24.693 106.404,24.693 107.376,25.664 107.376,28.09 SB18.2@107.417,28.131 C32.2@106.096,28.131 106.086,28.141 U2.1@104.581,28.141
WU_IRQ: SB11.1 SB36.1 SB38.2 | length 2.7
  Top Layer w0.254: SB36.1@202.648,50.93 203.001,50.93 203.846,50.93 ; SB38.2@204.203,50.935 204.556,50.935 205.392,50.935 205.736,50.935 SB11.1@205.741,50.93
WU_IRQ_TP: P12.2 Q5.1 R35.2 | length 10.8
  Bottom Layer w0.254: P12.2@208.648,22.775 209.17,22.775 209.433,23.038 213.782,23.038 R35.2@216.798,26.054 216.807,26.046 Q5.1@218.076,26.046
pads on no net: Fid1.0 Fid2.0 J1. J1.4 P1.3 P7.1 P7.2 P7.3 P7.4 P7.5 P8.1 P8.2 P8.3 P8.4 P8.5 P8.6 P8.7 P8.8 P12.1 P12.7 U1.9 U1.10 U1.11 U1.12 U1.14 U1.15 U1.16 U2.7 U3.2 U3.3 U3.9 U3.13 U3.15 U3.16 U4.0 U5.7 U5.10 U5.11 U5.15 U6.0 U7.11 U10.3 U10.10 U12.1 U12.10

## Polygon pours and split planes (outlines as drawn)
GND on Top Layer "Top_Layer-GND" (solid, remove dead copper, pour order 39): 6.282,6.397 -3.448,17.882 -3.45,37.982 8.761,50.193 10.199,50.193 180.296,50.193 186.365,56.262 298.374,56.262 298.374,56.201 298.374,-1.355 186.134,-1.355 178.381,6.397
GND on Bottom Layer "Bottom_Layer-GND" (solid, remove dead copper, pour order 37): -3.45,37.982 8.76,50.192 9.673,50.192 10.195,50.192 180.302,50.192 186.371,56.261 298.369,56.261 298.369,-1.346 186.104,-1.346 178.353,6.405 69.763,6.405 6.267,6.405 -3.45,17.895

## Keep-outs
Keep-Out Layer:
  circle w0.152: c11.7,19.432 r2.25
  circle w0.152: c11.7,35.432 r2.25
  circle w0.152: c22.417,27.432 r2.25
  circle w0.152: c84.905,27.45 r2.25
  circle w0.152: c188.21,3.243 r2.4
  circle w0.152: c240.28,36.263 r2.4
  circle w0.152: c189.48,51.503 r2.4
  circle w0.152: c240.28,8.323 r2.4
  circle w0.152: c270.76,3.243 r2.4
  circle w0.152: c264.41,51.503 r2.4
  circle w0.152: c11.7,35.432 r2.1
  circle w0.152: c153.1,27.432 r2.25
  lines w0.305: -0.01,20.349 ccw(c22.2,33.589) 22.2,7.732 59,7.732 cw(c88,-308.964) 117,7.732 ; 0,20.332 0,34.532 cw(c22.215,21.249) 22.2,47.132 59,47.132 ccw(c88,363.828) 117,47.132 179.892,47.132 187.624,54.864 293.3,54.864 293.3,41.089 295.84,38.549 295.84,5.783 293.3,3.243 293.3,0 187.624,0 179.876,7.748 116.999,7.748

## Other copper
Top Layer:
  pour cut-out: 126.266,35.17 126.266,33.523 126.266,33.178 125.997,33.447
  pour cut-out: 229.785,47.502 230.392,47.502 230.514,47.379
  pour cut-out: 227.467,48.133 226.863,47.529 226.575,47.529
Bottom Layer:
  pour cut-out: 278.794,4.863 274.787,4.863 274.787,1.863 278.794,1.863
  pour cut-out: 278.79,52.729 274.784,52.729 274.784,49.729 278.79,49.729

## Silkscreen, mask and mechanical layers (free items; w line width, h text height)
Top Overlay:
  lines w0.254: 179.876,7.748 179.892,7.765 ; 202.648,6.275 202.648,48.275 278.648,48.275 278.648,6.275 202.648,6.275
  text "nRF51" at 239.088,50.367 h0.69
  text "nRF52" at 248.758,50.367 h0.69
  text "NORDIC" at 8.595,29.431 h3.81
  text "SEMICONDUCTOR" at 8.509,27.94 h1.65
  text "400129" at 9.849,23.398 h2.03
  text "0049GETR" at 9.976,22.395 h0.64
Bottom Overlay:
  circle w0.102: c57.7,44.882 r0.398
  circle w0.102: c60.4,44.882 r0.403
  circle w0.102: c60.4,9.982 r0.403
  circle w0.102: c57.7,9.982 r0.398
  lines w0.102: 57.7,9.582 60.35,9.582 ; 57.7,10.382 60.4,10.382 ; 57.7,44.482 60.35,44.482 ; 57.7,45.282 60.4,45.282
Mechanical 1:
  lines w0.305: -0.01,20.349 ccw(c22.2,33.589) 22.2,7.732 59,7.732 cw(c88,-308.964) 117,7.732 ; 0,20.332 0,34.532 cw(c22.215,21.249) 22.2,47.132 59,47.132 ccw(c88,363.828) 117,47.132 179.892,47.132 187.624,54.864 293.3,54.864 293.3,41.089 295.84,38.549 295.84,5.783 293.3,3.243 293.3,0 187.624,0 179.876,7.748 116.999,7.748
